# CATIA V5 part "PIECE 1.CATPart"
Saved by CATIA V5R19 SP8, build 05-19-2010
Part number: PIECE 1
Bounding box of the stored display mesh (mm): x -17 to 0, y -12 to 12, z -11.818 to 11.818
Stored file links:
  C:\Users\ThinkMotion\Desktop\EU_thinkMotion\iao\IAO_MMS_Groupe3\jbuffard\jbuffard\PIECE 1.CATPart
  C:\Users\ThinkMotion\Desktop\EU_thinkMotion\iao\IAO_MMS_Groupe3\jbuffard\jbuffard\Mecanisme a coulisse a quatre elements de la griffe d'une camera.CATProduct
  C:\Users\ThinkMotion\Desktop\EU_thinkMotion\iao\IAO_MMS_Groupe3\jbuffard\jbuffard\BATI.CATPart
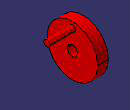
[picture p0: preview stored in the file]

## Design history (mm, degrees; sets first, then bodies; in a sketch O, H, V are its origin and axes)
External parameters (linked from other documents)
  `External.Diametre doigt/rainures` = 0.0015
Set1
  Plane1: linked copy from another document
  DatumCurve1: linked copy from another document
  Plane2: linked copy from another document
  Point1: linked copy from another document
Body1 (main body)
  Sketch1 on Plane1, origin (-12, 0, 0), H (0, 1, 0), V (0, 0, 1)
    circle A1 centre (0, 0) radius 2.5
    reference projected circle E1 centre (0, 0) radius 2.5 from edge of DatumCurve1
    circle A2 centre (0, 0) radius 12
    radius A2 = 12
    coincidence: A1 E1
    concentricity: A2 A1
  Pad1: profile Sketch1, direction (-1, 0, 0), up to Plane2
  Sketch2 on Plane1, origin (-12, 0, 0), H (0, 1, 0), V (0, 0, 1)
    circle A1 centre (0, 9) radius 1.5
    point P1 (0, 9)
    reference projected point E1 (0, 9) from Point1
    radius A1 = 1.5 {= `External.Diametre doigt/rainures`}
    coincidence: P1 E1
  Pad2: profile Sketch2, direction (1, 0, 0), up to yz-plane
